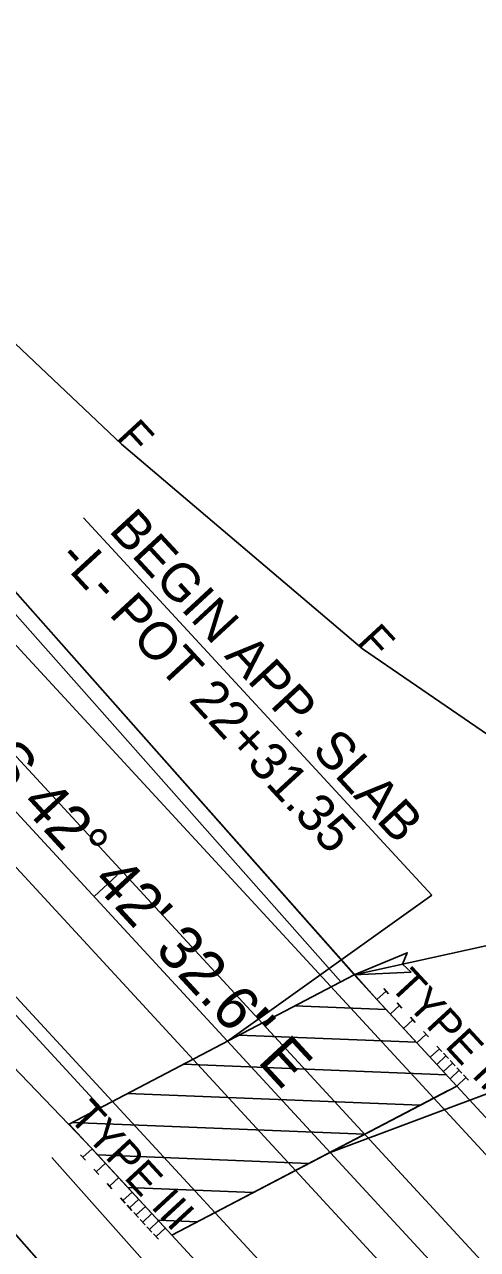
# Model space of a CAD drawing. Extents: x 1702862 to 1704514, y 793768 to 796215.
# Drawn here: x 1703456.9 to 1703529.1, y 795023.9 to 795219.2 of the extents above; entities that cross this region are included whole.
import ezdxf

# ---------------------------------------------------------------- set-up
doc = ezdxf.new("R2010")
doc.units = 0
for name, color, linetype in [('Old_Level_30', 7, 'Continuous'), ('Prop Approach Slab', 7, 'Continuous'), ('Prop Conc 2ft 6in Curb and Gutter', 7, 'Continuous'), ('Prop Conc Shoulder Berm Gutter', 7, 'Continuous'), ('Prop DSN Text', 7, 'Continuous'), ('Prop EOT', 7, 'Continuous'), ('Prop Guardrail', 7, 'Continuous'), ('Prop Guardrail Anchor Unit CELL', 7, 'Continuous'), ('Prop Horizontal Alignment', 7, 'Continuous'), ('Prop Horizontal Alignment Direction Label', 7, 'Continuous'), ('Prop Horizontal Alignment Tick Small', 7, 'Continuous'), ('Prop Lane Lines', 7, 'Continuous'), ('Prop Leader Line Medium', 7, 'Continuous'), ('Prop Paved Shoulder', 7, 'Continuous'), ('Prop Roadway Bridge', 7, 'Continuous'), ('Prop SS Fill Line', 7, 'Continuous'), ('Prop SS Misc', 7, 'Continuous'), ('Prop Structure Anchor Unit CELL', 7, 'Continuous'), ('Prop Terminator CELL', 7, 'Continuous')]:
    doc.layers.add(name, color=color, linetype=linetype)

msp = doc.modelspace()

# ---------------------------------------------------------------- linework, layer by layer
at = {"layer": 'Old_Level_30'}
msp.add_line((1703487.22, 795009.46), (1703461.25, 795038.56), dxfattribs=at)
at = {"layer": 'Prop Approach Slab'}
for p, q in [((1703464.03, 795043.92), (1703509.44, 795067.71)), ((1703509.44, 795067.71), (1703525.81, 795049.97)), ((1703499.96, 795062.74), (1703514.57, 795062.16)), ((1703491.08, 795058.09), (1703519.36, 795056.96)), ((1703482.21, 795053.44), (1703524.16, 795051.77)), ((1703473.33, 795048.79), (1703520, 795046.93)), ((1703480.41, 795026.18), (1703524.44, 795049.25)), ((1703480.41, 795026.18), (1703464.03, 795043.92)), ((1703464.46, 795044.15), (1703511.13, 795042.28)), ((1703468.6, 795038.98), (1703502.25, 795037.63)), ((1703473.39, 795033.78), (1703493.38, 795032.98)), ((1703478.19, 795028.58), (1703484.51, 795028.33))]:
    msp.add_line(p, q, dxfattribs=at)
msp.add_lwpolyline([(1703509.44, 795067.71), (1703525.81, 795049.97), (1703480.41, 795026.18), (1703464.03, 795043.92)], close=True, dxfattribs=at)
at = {"layer": 'Prop Conc 2ft 6in Curb and Gutter'}
for p in [(1703417.51, 795102.43), (1703468.49, 795047.2)]:
    msp.add_line(p, (1703469.08, 795046.57), dxfattribs=at)
at = {"layer": 'Prop Conc Shoulder Berm Gutter'}
msp.add_line((1703388.7, 795204.04), (1703509.44, 795067.71), dxfattribs=at)
at = {"layer": 'Prop EOT'}
for p, q in [((1703259.9, 795332.15), (1703737.14, 794815.13)), ((1703418.98, 795103.79), (1703636.58, 794868.05))]:
    msp.add_line(p, q, dxfattribs=at)
at = {"layer": 'Prop Guardrail'}
for p, q in [((1703513.1, 795063.75), (1703388.7, 795204.04)), ((1703450.36, 795057.99), (1703467.69, 795039.96))]:
    msp.add_line(p, q, dxfattribs=at)
at = {"layer": 'Prop Horizontal Alignment'}
msp.add_line((1703246.67, 795319.94), (1703723.92, 794802.92), dxfattribs=at)
at = {"layer": 'Prop Horizontal Alignment Tick Small'}
msp.add_line((1703468, 795080.17), (1703471.67, 795083.56), dxfattribs=at)
at = {"layer": 'Prop Lane Lines'}
for p, q in [((1703347.89, 795219.14), (1703550.56, 794999.58)), ((1703339.07, 795211), (1703542.22, 794990.92))]:
    msp.add_line(p, q, dxfattribs=at)
at = {"layer": 'Prop Leader Line Medium'}
for p, q in [((1703466.32, 795140.54), (1703521.83, 795080.4)), ((1703582.45, 795083.79), (1703509.44, 795067.71)), ((1703489.26, 795057.14), (1703521.83, 795080.4)), ((1703505.63, 795039.4), (1703615.49, 795080.46))]:
    msp.add_line(p, q, dxfattribs=at)
at = {"layer": 'Prop Paved Shoulder'}
for p, q in [((1703386.98, 795202.46), (1703507.31, 795066.6)), ((1703509.44, 795067.71), (1703525.81, 795049.97))]:
    msp.add_line(p, q, dxfattribs=at)
at = {"layer": 'Prop Roadway Bridge'}
for p, q in [((1703480.41, 795026.18), (1703525.81, 795049.97)), ((1703525.81, 795049.97), (1703658.78, 794905.92)), ((1703480.41, 795026.18), (1703613.32, 794882.19))]:
    msp.add_line(p, q, dxfattribs=at)
at = {"layer": 'Prop SS Fill Line'}
for p, q in [((1703435.98, 795186.71), (1703472.38, 795152.27)), ((1703472.38, 795152.27), (1703510.78, 795119.67)), ((1703510.78, 795119.67), (1703553.07, 795090.66)), ((1703434.77, 795049.5), (1703468.06, 795012.19))]:
    msp.add_line(p, q, dxfattribs=at)
at = {"layer": 'Prop Structure Anchor Unit CELL'}
for p, q in [((1703514.95, 795064.68), (1703514.18, 795065.53)), ((1703513.1, 795063.75), (1703514.57, 795065.11)), ((1703525.81, 795049.97), (1703513.1, 795063.75)), ((1703515.22, 795061.45), (1703516.69, 795062.81)), ((1703517.07, 795062.39), (1703516.3, 795063.23)), ((1703517.34, 795059.16), (1703518.81, 795060.51)), ((1703519.19, 795060.09), (1703518.42, 795060.93)), ((1703519.46, 795056.86), (1703520.93, 795058.22)), ((1703521.31, 795057.8), (1703520.54, 795058.64)), ((1703521.58, 795054.56), (1703523.04, 795055.92)), ((1703523.43, 795055.5), (1703522.66, 795056.34)), ((1703522.63, 795053.42), (1703524.1, 795054.77)), ((1703523.69, 795052.27), (1703525.16, 795053.62)), ((1703524.49, 795054.35), (1703523.72, 795055.19)), ((1703525.55, 795053.2), (1703524.78, 795054.04)), ((1703524.75, 795051.12), (1703526.22, 795052.48)), ((1703526.61, 795052.05), (1703525.84, 795052.9)), ((1703527.67, 795050.91), (1703526.9, 795051.75)), ((1703525.81, 795049.97), (1703527.28, 795051.33)), ((1703467.69, 795039.96), (1703466.22, 795038.61)), ((1703467.69, 795039.96), (1703466.22, 795038.61)), ((1703480.41, 795026.18), (1703467.69, 795039.96)), ((1703480.41, 795026.18), (1703467.69, 795039.96)), ((1703466.61, 795038.18), (1703465.83, 795039.03)), ((1703466.61, 795038.18), (1703465.83, 795039.03)), ((1703468.73, 795035.89), (1703467.95, 795036.73)), ((1703468.73, 795035.89), (1703467.95, 795036.73)), ((1703469.81, 795037.67), (1703468.34, 795036.31)), ((1703469.81, 795037.67), (1703468.34, 795036.31)), ((1703470.85, 795033.59), (1703470.07, 795034.43)), ((1703470.85, 795033.59), (1703470.07, 795034.43)), ((1703471.93, 795035.37), (1703470.46, 795034.01)), ((1703471.93, 795035.37), (1703470.46, 795034.01)), ((1703472.97, 795031.3), (1703472.19, 795032.14)), ((1703472.97, 795031.3), (1703472.19, 795032.14)), ((1703474.05, 795033.07), (1703472.58, 795031.72)), ((1703474.05, 795033.07), (1703472.58, 795031.72)), ((1703474.03, 795030.15), (1703473.25, 795030.99)), ((1703474.03, 795030.15), (1703473.25, 795030.99)), ((1703475.11, 795031.92), (1703473.64, 795030.57)), ((1703475.11, 795031.92), (1703473.64, 795030.57)), ((1703476.17, 795030.78), (1703474.7, 795029.42)), ((1703476.17, 795030.78), (1703474.7, 795029.42)), ((1703475.09, 795029), (1703474.31, 795029.84)), ((1703475.09, 795029), (1703474.31, 795029.84)), ((1703476.15, 795027.85), (1703475.37, 795028.69)), ((1703476.15, 795027.85), (1703475.37, 795028.69)), ((1703477.23, 795029.63), (1703475.76, 795028.27)), ((1703477.23, 795029.63), (1703475.76, 795028.27)), ((1703478.29, 795028.48), (1703476.82, 795027.12)), ((1703478.29, 795028.48), (1703476.82, 795027.12)), ((1703477.21, 795026.7), (1703476.43, 795027.54)), ((1703477.21, 795026.7), (1703476.43, 795027.54)), ((1703478.27, 795025.56), (1703477.49, 795026.4)), ((1703478.27, 795025.56), (1703477.49, 795026.4)), ((1703479.35, 795027.33), (1703477.88, 795025.98)), ((1703479.35, 795027.33), (1703477.88, 795025.98))]:
    msp.add_line(p, q, dxfattribs=at)
at = {"layer": 'Prop Terminator CELL'}
msp.add_lwpolyline([(1703518.56, 795068.13), (1703509.44, 795067.71), (1703517.93, 795071.22), (1703517.16, 795069.41)], close=True, dxfattribs=at)

# ---------------------------------------------------------------- texts
at = {"layer": 'Prop DSN Text'}
for s, p in [(' BEGIN APP. SLAB', (1703468.68, 795140.08)), ('-L- POT 22+31.35', (1703462.07, 795133.97))]:
    msp.add_text(s, height=6, rotation=312.7091, dxfattribs=at).set_placement(p)
at = {"layer": 'Prop Guardrail Anchor Unit CELL'}
for p in [(1703514.95, 795065.82), (1703463.8, 795044.87)]:
    msp.add_text('TYPE III', height=5, rotation=312.7301, dxfattribs=at).set_placement(p)
at = {"layer": 'Prop Horizontal Alignment Direction Label'}
msp.add_text('S 42%%d 42\' 32.6" E', height=7, rotation=312.7091, dxfattribs=at).set_placement((1703450.14, 795101.27))
at = {"layer": 'Prop SS Misc'}
for p in [(1703471.42, 795153.31), (1703509.82, 795120.71)]:
    msp.add_text('F', height=5, rotation=312.7091, dxfattribs=at).set_placement(p)

doc.saveas('drawing.dxf')
